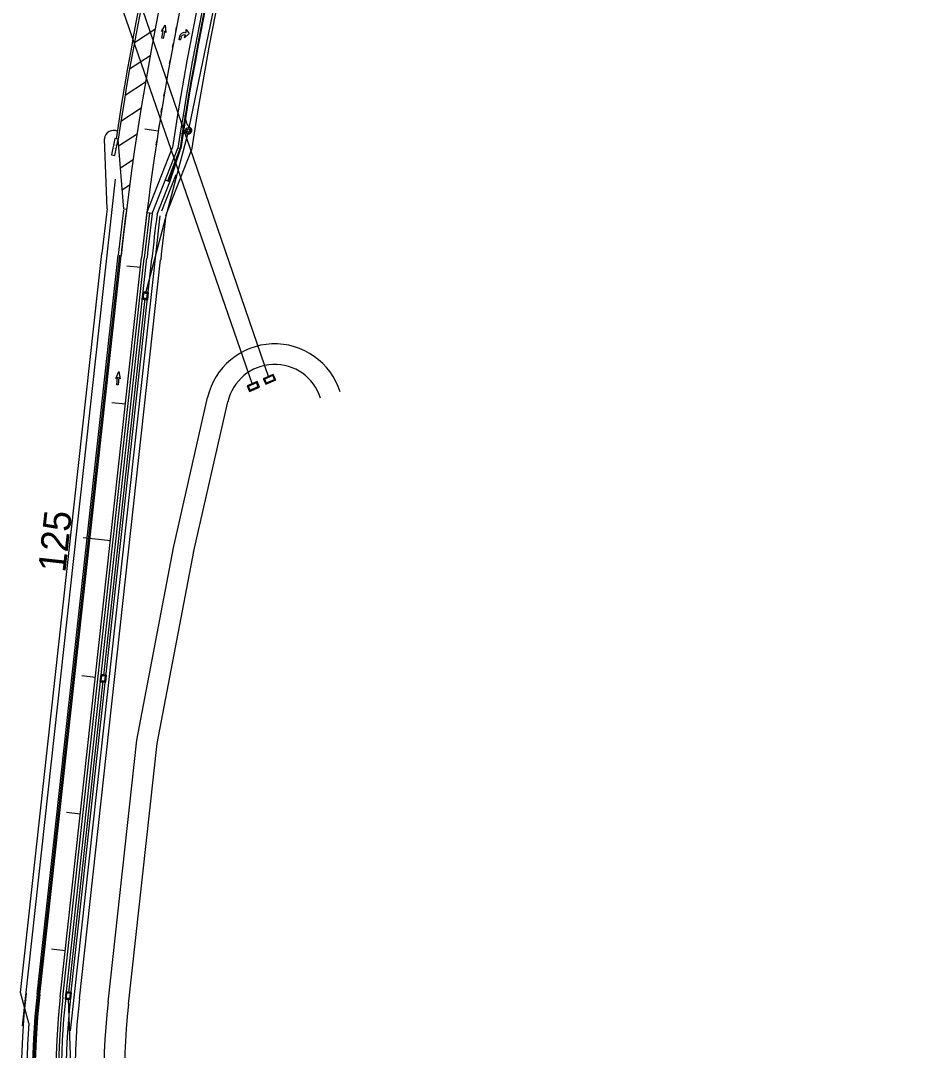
# Model space of a CAD drawing. Extents: x 468143 to 491361, y 1438528 to 1468730.
# Drawn here: x 487595 to 488239, y 1465730 to 1466479 of the extents above; entities that cross this region are included whole.
import ezdxf

# ---------------------------------------------------------------- set-up
doc = ezdxf.new("R2010")
doc.units = 0
doc.layers.add('Default', color=7, linetype='Continuous')
doc.layers.add('Xreference_dp', color=7, linetype='Continuous')

# ---------------------------------------------------------------- blocks, each defined once
blk = doc.blocks.new('POINT_DISPLAY')
at = {"layer": 'Default'}
blk.add_line((0, 0), (0, 0), dxfattribs=at)
blk = doc.blocks.new('DAMerge_6')
at = {"layer": 'Default'}
blk.add_lwpolyline([(0.71, -4.09), (0, -3.39), (3.95, 0.56), (2.42, 0.68), (7.31, 3.21), (4.77, -1.68), (4.66, -0.15), (0.71, -4.09)], dxfattribs=at)
blk = doc.blocks.new('DALeftTurn_5')
at = {"layer": 'Default'}
for points in [[(5.67, 3.17), (2, 0.5), (4.33, 0.83), (4.33, 0.17)], [(6, 0.17), (6, 0.83), (8.25, 0.5), (5.67, 3.17)], [(2, -2.17), (0, -2.17), (0, -3.17), (2.67, -3.17)]]:
    blk.add_lwpolyline(points, dxfattribs=at)
for centre, radius in [((2, 0.17), 2.33), ((2.67, 0.17), 3.33)]:
    blk.add_arc(centre, radius, 270, 0, dxfattribs=at)

msp = doc.modelspace()

# ---------------------------------------------------------------- linework, layer by layer
at = {"layer": 'Xreference_dp'}
for p, q in [((487760.83, 1466611.39), (487717.03, 1466401.07)), ((487775.14, 1466219.46), (487676.31, 1466507.76)), ((487763.29, 1466214.22), (487667.1, 1466492.47)), ((487707.49, 1466471.39), (487708.06, 1466474.33)), ((487677.42, 1466463.02), (487692.32, 1466472.75)), ((487705.27, 1466459.6), (487705.82, 1466462.55)), ((487673.97, 1466443.87), (487688.92, 1466453.64)), ((487703.11, 1466447.79), (487703.64, 1466450.75)), ((487701.02, 1466435.98), (487701.53, 1466438.93)), ((487670.72, 1466424.86), (487685.54, 1466434.54)), ((487698.99, 1466424.15), (487699.49, 1466427.11)), ((487667.67, 1466405.97), (487682.37, 1466415.58)), ((487697.04, 1466412.31), (487697.52, 1466415.27)), ((487714.33, 1466409.59), (487712.31, 1466396.75)), ((487714.82, 1466409.51), (487712.84, 1466409.82)), ((487694.84, 1466398.48), (487684.96, 1466400.02)), ((487695.15, 1466400.46), (487695.62, 1466403.42)), ((487657.65, 1466342.16), (487655.69, 1466393.03)), ((487665.64, 1466392.76), (487664.12, 1466392.99)), ((487669.72, 1466341.79), (487665.64, 1466392.76)), ((487666.02, 1466388.01), (487679.4, 1466396.74)), ((487716.41, 1466397.11), (487685.61, 1466280.82)), ((487693.33, 1466388.6), (487693.78, 1466391.56)), ((487710.82, 1466396.98), (487712.8, 1466396.67)), ((487712.8, 1466396.67), (487712.88, 1466397.16)), ((487712.88, 1466397.16), (487716.33, 1466396.62)), ((487686.49, 1466339.07), (487705.2, 1466386.81)), ((487690.46, 1466338.57), (487709.15, 1466386.22)), ((487700.38, 1466337.32), (487719.04, 1466384.73)), ((487701.84, 1466362.37), (487710.64, 1466385.99)), ((487702.31, 1466362.19), (487710.64, 1466385.99)), ((487703.24, 1466361.83), (487711.13, 1466385.92)), ((487711.13, 1466385.92), (487709.15, 1466386.22)), ((487667.31, 1466371.95), (487676.61, 1466378.03)), ((487596.05, 1465747.83), (487663.79, 1466363.71)), ((487693.93, 1466338.13), (487703.24, 1466361.83)), ((487697.47, 1466340.65), (487707.92, 1466367.16)), ((487700.07, 1466363.07), (487703.24, 1466361.83)), ((487668.59, 1466355.9), (487674.02, 1466359.45)), ((487671.68, 1466341.48), (487669.72, 1466341.79)), ((487690.46, 1466338.57), (487686.51, 1466339.18)), ((487631.04, 1465744.17), (487696.25, 1466337.05)), ((487594.69, 1465772), (487653.82, 1466309.69)), ((487606.62, 1465770.69), (487665.75, 1466308.38)), ((487607.61, 1465770.58), (487666.75, 1466308.27)), ((487608.6, 1465770.47), (487667.74, 1466308.16)), ((487608.6, 1465770.47), (487667.74, 1466308.16)), ((487623.51, 1465768.83), (487682.65, 1466306.52)), ((487623.51, 1465768.83), (487682.65, 1466306.52)), ((487623.51, 1465768.83), (487682.65, 1466306.52)), ((487625.5, 1465768.61), (487684.64, 1466306.3)), ((487627.49, 1465768.4), (487686.63, 1466306.08)), ((487630.97, 1465768.01), (487690.11, 1466305.7)), ((487637.43, 1465767.3), (487696.57, 1466304.99)), ((487681.86, 1466299.34), (487671.92, 1466300.43)), ((487683.57, 1466281.71), (487682.99, 1466276.41)), ((487684.01, 1466281.16), (487683.54, 1466276.85)), ((487687.79, 1466281.25), (487683.57, 1466281.71)), ((487684.12, 1466280.65), (487683.76, 1466277.33)), ((487687.24, 1466280.81), (487684.01, 1466281.16)), ((487687.02, 1466280.33), (487684.12, 1466280.65)), ((487684.23, 1466281.64), (487684.18, 1466281.14)), ((487685.68, 1466281.48), (487685.57, 1466280.49)), ((487686.66, 1466277.01), (487687.02, 1466280.33)), ((487686.77, 1466276.5), (487687.24, 1466280.81)), ((487687.08, 1466280.82), (487687.13, 1466281.32)), ((487687.21, 1466275.95), (487687.79, 1466281.25)), ((487685.17, 1466276.84), (487655, 1466002.5)), ((487682.99, 1466276.41), (487687.21, 1466275.95)), ((487683.54, 1466276.85), (487686.77, 1466276.5)), ((487683.7, 1466276.84), (487683.65, 1466276.34)), ((487683.76, 1466277.33), (487686.66, 1466277.01)), ((487685.1, 1466276.18), (487685.21, 1466277.17)), ((487686.55, 1466276.02), (487686.6, 1466276.52)), ((487778.49, 1466221.66), (487771.25, 1466218.48)), ((487771.25, 1466218.48), (487772.99, 1466214.51)), ((487778.07, 1466220.98), (487772.04, 1466218.33)), ((487772.04, 1466218.33), (487773.41, 1466215.2)), ((487778.15, 1466220.79), (487772.12, 1466218.14)), ((487779.44, 1466217.85), (487778.07, 1466220.98)), ((487780.24, 1466217.7), (487778.49, 1466221.66)), ((487766.65, 1466216.43), (487759.4, 1466213.24)), ((487759.4, 1466213.24), (487761.15, 1466209.28)), ((487766.22, 1466215.74), (487760.2, 1466213.09)), ((487760.2, 1466213.09), (487761.57, 1466209.96)), ((487766.31, 1466215.55), (487760.28, 1466212.9)), ((487761.15, 1466209.28), (487768.39, 1466212.46)), ((487761.49, 1466210.15), (487767.51, 1466212.8)), ((487761.57, 1466209.96), (487767.6, 1466212.61)), ((487767.6, 1466212.61), (487766.22, 1466215.74)), ((487768.39, 1466212.46), (487766.65, 1466216.43)), ((487772.99, 1466214.51), (487780.24, 1466217.7)), ((487773.33, 1466215.39), (487779.36, 1466218.04)), ((487773.41, 1466215.2), (487779.44, 1466217.85)), ((487705.93, 1466095.49), (487730.73, 1466204.91)), ((487670.93, 1466199.94), (487660.99, 1466201.03)), ((487720.56, 1466092.17), (487745.36, 1466201.59)), ((487660, 1466100.54), (487640.12, 1466102.72)), ((487679.25, 1465955.45), (487705.93, 1466095.49)), ((487694.1, 1465953.22), (487720.66, 1466092.68)), ((487649.06, 1466001.14), (487639.12, 1466002.23)), ((487652.96, 1466003.39), (487652.38, 1465998.09)), ((487653.4, 1466002.84), (487652.93, 1465998.53)), ((487657.18, 1466002.93), (487652.96, 1466003.39)), ((487653.51, 1466002.32), (487653.15, 1465999.01)), ((487656.63, 1466002.48), (487653.4, 1466002.84)), ((487656.41, 1466002.01), (487653.51, 1466002.32)), ((487653.62, 1466003.32), (487653.57, 1466002.82)), ((487655.07, 1466003.16), (487654.96, 1466002.16)), ((487656.05, 1465998.69), (487656.41, 1466002.01)), ((487656.16, 1465998.18), (487656.63, 1466002.48)), ((487656.47, 1466002.5), (487656.52, 1466003)), ((487656.6, 1465997.62), (487657.18, 1466002.93)), ((487654.56, 1465998.52), (487629.61, 1465771.64)), ((487652.38, 1465998.09), (487656.6, 1465997.62)), ((487652.93, 1465998.53), (487656.16, 1465998.18)), ((487653.09, 1465998.51), (487653.04, 1465998.02)), ((487653.15, 1465999.01), (487656.05, 1465998.69)), ((487654.49, 1465997.86), (487654.6, 1465998.85)), ((487655.94, 1465997.7), (487655.99, 1465998.19)), ((487658.3, 1465765.01), (487679.25, 1465955.45)), ((487673.21, 1465763.37), (487694.1, 1465953.22)), ((487638.13, 1465901.74), (487628.19, 1465902.83)), ((487627.2, 1465802.34), (487617.26, 1465803.43)), ((487600.69, 1465749.77), (487594.69, 1465772)), ((487627.57, 1465772.53), (487626.99, 1465767.23)), ((487628.01, 1465771.98), (487627.54, 1465767.67)), ((487631.79, 1465772.07), (487627.57, 1465772.53)), ((487628.12, 1465771.47), (487627.76, 1465768.15)), ((487631.24, 1465771.63), (487628.01, 1465771.98)), ((487631.02, 1465771.15), (487628.12, 1465771.47)), ((487628.23, 1465772.46), (487628.18, 1465771.96)), ((487629.68, 1465772.3), (487629.57, 1465771.31)), ((487630.66, 1465767.83), (487631.02, 1465771.15)), ((487630.77, 1465767.32), (487631.24, 1465771.63)), ((487631.08, 1465771.64), (487631.13, 1465772.14)), ((487631.21, 1465766.77), (487631.79, 1465772.07)), ((487626.99, 1465767.23), (487631.21, 1465766.77)), ((487627.54, 1465767.67), (487630.77, 1465767.32)), ((487627.7, 1465767.66), (487627.65, 1465767.16)), ((487627.76, 1465768.15), (487630.66, 1465767.83)), ((487629.1, 1465767), (487629.21, 1465767.99)), ((487629.17, 1465767.66), (487635.28, 1465606.32)), ((487630.55, 1465766.84), (487630.6, 1465767.34))]:
    msp.add_line(p, q, dxfattribs=at)
for points in [[(487665.64, 1466392.76), (487663.19, 1466393.24), (487660.9, 1466381.46), (487663.35, 1466380.98)], [(487684.16, 1466280.98), (487683.72, 1466277), (487686.62, 1466276.68), (487687.06, 1466280.66)], [(487653.55, 1466002.66), (487653.11, 1465998.68), (487656.01, 1465998.36), (487656.45, 1466002.34)], [(487628.16, 1465771.8), (487627.72, 1465767.82), (487630.62, 1465767.5), (487631.06, 1465771.48)]]:
    msp.add_lwpolyline(points, close=True, dxfattribs=at)
for radius in [2, 1]:
    msp.add_circle((487716.72, 1466399.09), radius, dxfattribs=at)
for centre, radius, start, end in [((489753.65, 1466078.75), 2083.48, 155.36712, 173.72367), ((489753.65, 1466078.75), 2113.02, 160.1724, 171.4474), ((489753.65, 1466078.75), 2111.48, 160.1724, 171.4474), ((489753.65, 1466078.75), 2098.48, 160.1724, 173.72367), ((489753.65, 1466078.75), 2071.48, 160.1724, 171.4474), ((489753.65, 1466078.75), 2067.48, 160.1724, 171.4474), ((489753.65, 1466078.75), 2065.98, 160.1724, 171.4474), ((489753.65, 1466078.75), 2065.48, 160.1724, 171.4474), ((489753.65, 1466078.75), 2057.48, 160.1724, 171.4474), ((487724.71, 1466408.06), 10, 171.63406, 220.52455), ((487662.33, 1466392.43), 6.67, 64.31195, 174.80281), ((487716.72, 1466399.09), 2.5, 261.0624, 81.0624), ((489753.65, 1466078.75), 2112.48, 172.83688, 173.72367), ((489753.65, 1466078.75), 2100.48, 172.8224, 173.72367), ((489753.65, 1466078.75), 2100.48, 172.8224, 173.72367), ((489753.65, 1466078.75), 2098.48, 172.8224, 173.72367), ((489753.65, 1466078.75), 2083.48, 172.8224, 173.72367), ((489753.65, 1466078.75), 2083.48, 172.8224, 173.72367), ((489753.65, 1466078.75), 2081.48, 172.8224, 173.72367), ((489753.65, 1466078.75), 2079.48, 172.8224, 173.72367), ((489753.65, 1466078.75), 2075.98, 172.8224, 173.72367), ((489753.65, 1466078.75), 2069.48, 172.8224, 173.72367), ((487779.5, 1466193.86), 50, 17.45047, 167.22851), ((487779.5, 1466193.86), 35, 17.45047, 167.22851), ((488179.15, 1465707.72), 583.98, 173.72367, 272.61758), ((488179.15, 1465707.72), 575.98, 173.72367, 275.96561), ((488179.15, 1465707.72), 574.98, 173.72367, 275.96561), ((488179.15, 1465707.72), 573.98, 173.72367, 275.96561), ((488179.15, 1465707.72), 573.98, 173.72367, 275.96561), ((488179.15, 1465707.72), 558.98, 173.72367, 275.96561), ((488179.15, 1465707.72), 558.98, 173.72367, 275.96561), ((488179.15, 1465707.72), 558.98, 173.72367, 275.96561), ((488179.15, 1465707.72), 556.98, 173.72367, 275.96561), ((488179.15, 1465707.72), 554.98, 173.72367, 275.96561), ((488179.15, 1465707.72), 551.48, 173.72367, 205.11898), ((488179.15, 1465707.72), 544.98, 173.72367, 205.11898), ((488179.15, 1465707.72), 523.98, 173.72367, 236.35666), ((488179.15, 1465707.72), 508.98, 173.72367, 236.35666), ((488179.15, 1465707.72), 579.98, 175.84236, 274.50155)]:
    msp.add_arc(centre, radius, start, end, dxfattribs=at)

# ---------------------------------------------------------------- block references
for name, p, rotation in [('DAMerge_6', (487695.54, 1466469.07), 33.84594838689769), ('POINT_DISPLAY', (487711.29, 1466399.95), -98.9376042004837), ('POINT_DISPLAY', (487711.29, 1466399.95), -98.9376042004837), ('POINT_DISPLAY', (487714.75, 1466399.4), -98.9376042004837), ('POINT_DISPLAY', (487714.75, 1466399.4), -98.9376042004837), ('POINT_DISPLAY', (487714.78, 1466398.64), -98.9376042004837), ('POINT_DISPLAY', (487715.04, 1466400.17), -98.9376042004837), ('POINT_DISPLAY', (487715.57, 1466400.72), -98.9376042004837), ('POINT_DISPLAY', (487716.27, 1466401.04), -98.9376042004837), ('POINT_DISPLAY', (487716.72, 1466399.09), -98.9376042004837), ('POINT_DISPLAY', (487716.72, 1466399.09), -98.9376042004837), ('POINT_DISPLAY', (487717.03, 1466401.07), -98.9376042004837), ('POINT_DISPLAY', (487717.03, 1466401.07), -98.9376042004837), ('POINT_DISPLAY', (487717.8, 1466400.77), -98.9376042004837), ('POINT_DISPLAY', (487718.36, 1466400.24), -98.9376042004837), ('POINT_DISPLAY', (487718.41, 1466398.01), -98.9376042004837), ('POINT_DISPLAY', (487718.67, 1466399.55), -98.9376042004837), ('POINT_DISPLAY', (487718.7, 1466398.78), -98.9376042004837), ('POINT_DISPLAY', (487718.7, 1466398.78), -98.9376042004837), ('POINT_DISPLAY', (487719.19, 1466398.7), -98.9376042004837), ('POINT_DISPLAY', (487715.09, 1466397.94), -98.9376042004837), ('POINT_DISPLAY', (487715.64, 1466397.41), -98.9376042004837), ('POINT_DISPLAY', (487716.41, 1466397.11), -98.9376042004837), ('POINT_DISPLAY', (487716.41, 1466397.11), -98.9376042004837), ('POINT_DISPLAY', (487717.18, 1466397.14), -98.9376042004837), ('POINT_DISPLAY', (487717.88, 1466397.46), -98.9376042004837), ('POINT_DISPLAY', (487683.28, 1466279.06), -96.2763279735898), ('POINT_DISPLAY', (487683.94, 1466278.99), -96.2763279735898), ('POINT_DISPLAY', (487683.94, 1466278.99), -96.2763279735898), ('POINT_DISPLAY', (487684.16, 1466280.98), -96.2763279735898), ('POINT_DISPLAY', (487685.39, 1466278.83), -96.2763279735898), ('POINT_DISPLAY', (487685.39, 1466278.83), -96.2763279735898), ('POINT_DISPLAY', (487685.61, 1466280.82), -96.2763279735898), ('POINT_DISPLAY', (487685.61, 1466280.82), -96.2763279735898), ('POINT_DISPLAY', (487686.84, 1466278.67), -96.2763279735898), ('POINT_DISPLAY', (487686.84, 1466278.67), -96.2763279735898), ('POINT_DISPLAY', (487687.06, 1466280.66), -96.2763279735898), ('POINT_DISPLAY', (487687.5, 1466278.6), -96.2763279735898), ('POINT_DISPLAY', (487683.72, 1466277), -96.2763279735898), ('POINT_DISPLAY', (487685.17, 1466276.84), -96.2763279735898), ('POINT_DISPLAY', (487685.17, 1466276.84), -96.2763279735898), ('POINT_DISPLAY', (487686.62, 1466276.68), -96.2763279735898), ('DAMerge_6', (487662.43, 1466216.68), 39.51374922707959), ('POINT_DISPLAY', (487773.54, 1466218.76), -156.27632797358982), ('POINT_DISPLAY', (487774.87, 1466220.07), -156.27632797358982), ('POINT_DISPLAY', (487775.14, 1466219.46), -156.27632797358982), ('POINT_DISPLAY', (487775.14, 1466219.46), -156.27632797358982), ('POINT_DISPLAY', (487776.74, 1466220.17), -156.27632797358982), ('POINT_DISPLAY', (487778.15, 1466220.79), -156.27632797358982), ('POINT_DISPLAY', (487778.75, 1466219.41), -156.27632797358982), ('POINT_DISPLAY', (487778.75, 1466219.41), -156.27632797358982), ('POINT_DISPLAY', (487760.28, 1466212.9), -156.27632797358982), ('POINT_DISPLAY', (487760.88, 1466211.53), -156.27632797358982), ('POINT_DISPLAY', (487761.69, 1466213.52), -156.27632797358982), ('POINT_DISPLAY', (487762.9, 1466210.77), -156.27632797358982), ('POINT_DISPLAY', (487763.03, 1466214.84), -156.27632797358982), ('POINT_DISPLAY', (487763.29, 1466214.22), -156.27632797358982), ('POINT_DISPLAY', (487763.29, 1466214.22), -156.27632797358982), ('POINT_DISPLAY', (487763.9, 1466212.85), -156.27632797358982), ('POINT_DISPLAY', (487763.9, 1466212.85), -156.27632797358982), ('POINT_DISPLAY', (487764.5, 1466211.48), -156.27632797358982), ('POINT_DISPLAY', (487764.5, 1466211.48), -156.27632797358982), ('POINT_DISPLAY', (487764.77, 1466210.87), -156.27632797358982), ('POINT_DISPLAY', (487764.9, 1466214.93), -156.27632797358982), ('POINT_DISPLAY', (487766.1, 1466212.18), -156.27632797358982), ('POINT_DISPLAY', (487766.31, 1466215.55), -156.27632797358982), ('POINT_DISPLAY', (487766.91, 1466214.18), -156.27632797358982), ('POINT_DISPLAY', (487766.91, 1466214.18), -156.27632797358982), ('POINT_DISPLAY', (487767.51, 1466212.81), -156.27632797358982), ('POINT_DISPLAY', (487772.12, 1466218.14), -156.27632797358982), ('POINT_DISPLAY', (487772.73, 1466216.76), -156.27632797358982), ('POINT_DISPLAY', (487773.33, 1466215.39), -156.27632797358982), ('POINT_DISPLAY', (487774.74, 1466216.01), -156.27632797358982), ('POINT_DISPLAY', (487775.74, 1466218.09), -156.27632797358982), ('POINT_DISPLAY', (487775.74, 1466218.09), -156.27632797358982), ('POINT_DISPLAY', (487776.34, 1466216.71), -156.27632797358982), ('POINT_DISPLAY', (487776.34, 1466216.71), -156.27632797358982), ('POINT_DISPLAY', (487776.61, 1466216.1), -156.27632797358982), ('POINT_DISPLAY', (487777.95, 1466217.42), -156.27632797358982), ('POINT_DISPLAY', (487779.35, 1466218.04), -156.27632797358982), ('POINT_DISPLAY', (487761.49, 1466210.15), -156.27632797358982), ('POINT_DISPLAY', (487653.55, 1466002.66), -96.2763279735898), ('POINT_DISPLAY', (487655, 1466002.5), -96.2763279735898), ('POINT_DISPLAY', (487655, 1466002.5), -96.2763279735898), ('POINT_DISPLAY', (487656.45, 1466002.34), -96.2763279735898), ('POINT_DISPLAY', (487652.67, 1466000.74), -96.2763279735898), ('POINT_DISPLAY', (487653.11, 1465998.68), -96.2763279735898), ('POINT_DISPLAY', (487653.33, 1466000.67), -96.2763279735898), ('POINT_DISPLAY', (487653.33, 1466000.67), -96.2763279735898), ('POINT_DISPLAY', (487654.56, 1465998.52), -96.2763279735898), ('POINT_DISPLAY', (487654.56, 1465998.52), -96.2763279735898), ('POINT_DISPLAY', (487654.78, 1466000.51), -96.2763279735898), ('POINT_DISPLAY', (487654.78, 1466000.51), -96.2763279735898), ('POINT_DISPLAY', (487656.01, 1465998.36), -96.2763279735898), ('POINT_DISPLAY', (487656.23, 1466000.35), -96.2763279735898), ('POINT_DISPLAY', (487656.23, 1466000.35), -96.2763279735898), ('POINT_DISPLAY', (487656.89, 1466000.28), -96.2763279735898), ('POINT_DISPLAY', (487627.28, 1465769.88), -96.2763279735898), ('POINT_DISPLAY', (487627.94, 1465769.81), -96.2763279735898), ('POINT_DISPLAY', (487627.94, 1465769.81), -96.2763279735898), ('POINT_DISPLAY', (487628.16, 1465771.8), -96.2763279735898), ('POINT_DISPLAY', (487629.39, 1465769.65), -96.2763279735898), ('POINT_DISPLAY', (487629.39, 1465769.65), -96.2763279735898), ('POINT_DISPLAY', (487629.61, 1465771.64), -96.2763279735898), ('POINT_DISPLAY', (487629.61, 1465771.64), -96.2763279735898), ('POINT_DISPLAY', (487630.84, 1465769.49), -96.2763279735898), ('POINT_DISPLAY', (487630.84, 1465769.49), -96.2763279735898), ('POINT_DISPLAY', (487631.06, 1465771.48), -96.2763279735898), ('POINT_DISPLAY', (487631.5, 1465769.42), -96.2763279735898), ('POINT_DISPLAY', (487627.72, 1465767.82), -96.2763279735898), ('POINT_DISPLAY', (487629.17, 1465767.66), -96.2763279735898), ('POINT_DISPLAY', (487629.17, 1465767.66), -96.2763279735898), ('POINT_DISPLAY', (487630.62, 1465767.5), -96.2763279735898)]:
    msp.add_blockref(name, p, dxfattribs=dict(at, rotation=rotation))
at = {"layer": 'Xreference_dp', "yscale": -1.0000000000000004, "rotation": 79.5924447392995}
msp.add_blockref('DALeftTurn_5', (487713.15, 1466464.56), dxfattribs=at)

# ---------------------------------------------------------------- texts
at = {"layer": 'Xreference_dp'}
for s, height, rotation, p in [('C.   C.', 1, 78.14705, (487663.44, 1466385.49)), ('125', 20, 83.72367, (487627.23, 1466077.04))]:
    msp.add_text(s, height=height, rotation=rotation, dxfattribs=at).set_placement(p)

doc.saveas('drawing.dxf')
